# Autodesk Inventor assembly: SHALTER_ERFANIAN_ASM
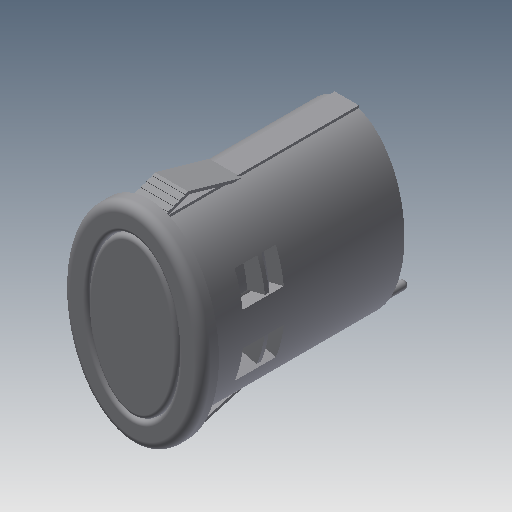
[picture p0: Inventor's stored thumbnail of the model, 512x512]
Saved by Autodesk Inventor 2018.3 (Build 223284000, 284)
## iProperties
Created: 2019-01
Part Number: SHALTER_ERFANIAN_ASM
Material: Generisch
Document SubType Name: Assembly
Designer: zand
Author: zand
Revision Number: 7LAST_VERSION
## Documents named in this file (3)
- D:\10_CAD-ÜBUNGEN\KAFFEEMASCHINE\Workspaces\Arbeitsbereich\SHALTER_ERFANIAN_ASM.iam
- D:\10_CAD-ÜBUNGEN\KAFFEEMASCHINE\Workspaces\Arbeitsbereich\SCHLATERGEHAEUSE_ERFANIAN.ipt
- D:\10_CAD-ÜBUNGEN\KAFFEEMASCHINE\Workspaces\Arbeitsbereich\LICHT_ROT_ERFANIAN.ipt
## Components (2 placed, 2 different names)
1. Schaltergehaeuse
2. Licht_rot
